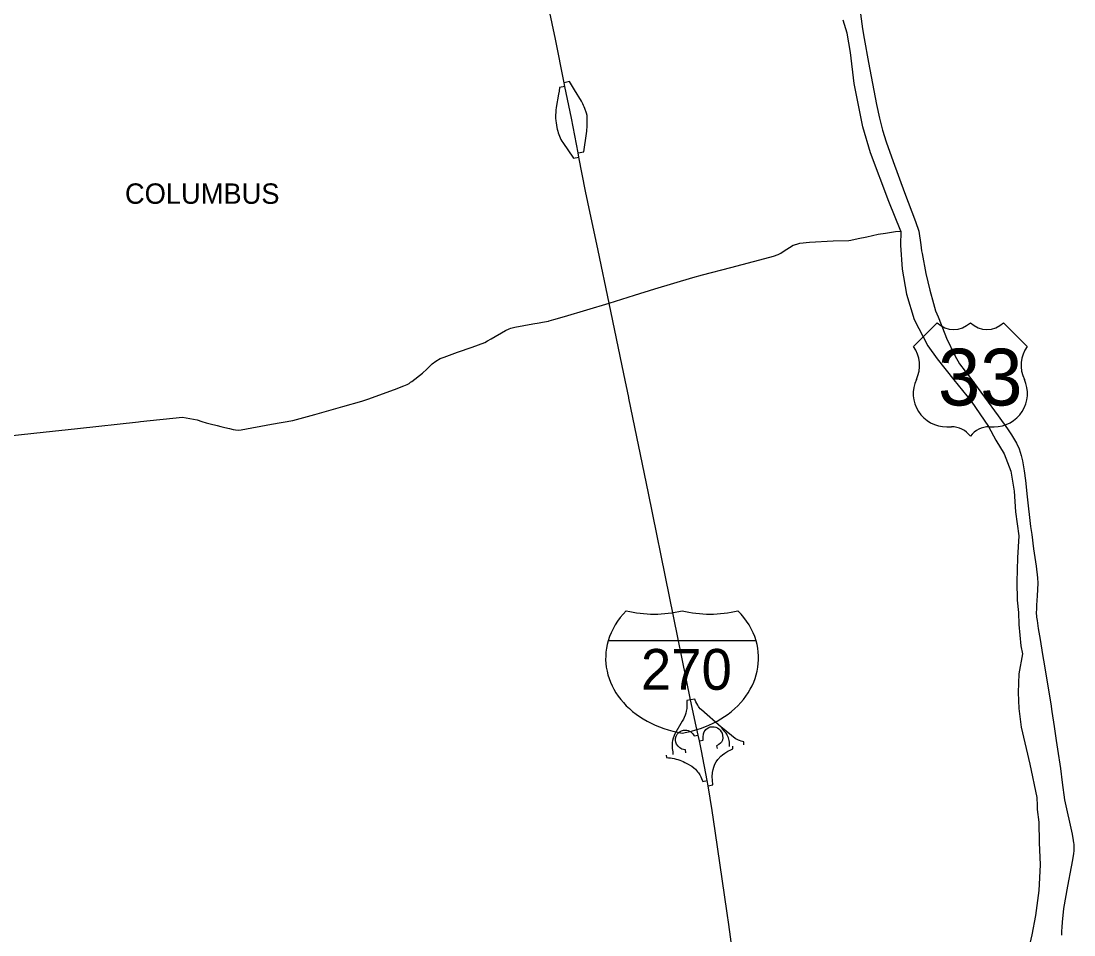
# Model space of a CAD drawing. Extents: x -1146 to -445, y -1283 to -822.
# Drawn here: x -1012.2 to -947.7, y -1003.9 to -947.9 of the extents above; entities that cross this region are included whole.
import ezdxf

# ---------------------------------------------------------------- set-up
doc = ezdxf.new("R2010")
doc.units = 0
for name, color, linetype in [('GM_X_Corporation_Text', 7, 'Continuous'), ('GM_X_Interchange_Ramps', 7, 'Continuous'), ('GM_X_Interstate_Route', 7, 'Continuous'), ('GM_X_Interstate_Shield', 7, 'Continuous'), ('GM_X_Township', 7, 'Continuous'), ('GM_X_US_Route', 7, 'Continuous'), ('GM_X_US_Shield', 7, 'Continuous')]:
    doc.layers.add(name, color=color, linetype=linetype)

msp = doc.modelspace()

# ---------------------------------------------------------------- linework, layer by layer
at = {"layer": 'GM_X_Interchange_Ramps'}
for points in [[(-978.902, -951.89), (-979.229, -951.959), (-979.255, -952.192), (-979.289, -952.371), (-979.433, -953.182), (-979.457, -953.352), (-979.468, -953.51), (-979.47, -953.61), (-979.477, -953.836), (-979.465, -954.004)], [(-977.548, -953.678), (-977.581, -953.535), (-977.686, -953.251), (-977.723, -953.152), (-977.762, -953.058), (-977.811, -952.953), (-977.896, -952.795), (-978.31, -952.113), (-978.444, -951.905), (-978.629, -951.601), (-978.945, -951.667)], [(-979.465, -954.004), (-979.447, -954.123), (-979.396, -954.415), (-979.375, -954.521), (-979.346, -954.638), (-979.316, -954.74), (-979.281, -954.84), (-979.242, -954.937), (-979.196, -955.04), (-979.143, -955.144), (-979.085, -955.245), (-979.034, -955.326), (-978.369, -956.3), (-978.043, -956.235)], [(-978.094, -955.977), (-977.747, -955.908), (-977.587, -954.786), (-977.564, -954.641), (-977.552, -954.528), (-977.546, -954.407), (-977.531, -953.796), (-977.548, -953.678)], [(-971.203, -989.506), (-971.428, -989.551), (-971.423, -989.758), (-971.426, -989.925), (-971.437, -990.045), (-971.461, -990.194), (-971.491, -990.321), (-971.531, -990.45), (-971.586, -990.591), (-971.631, -990.687), (-971.707, -990.824), (-972.176, -991.636), (-972.228, -991.751), (-972.268, -991.863), (-972.302, -991.991), (-972.324, -992.126), (-972.333, -992.232), (-972.333, -992.366), (-972.322, -992.487), (-972.307, -992.589), (-972.285, -992.705), (-972.279, -992.86)], [(-967.926, -992.257), (-967.944, -992.072), (-968.097, -992.038), (-968.192, -992.009), (-968.269, -991.979), (-968.342, -991.946), (-968.399, -991.917), (-968.466, -991.877), (-969.249, -991.238), (-969.318, -991.181), (-970.536, -990.128), (-970.605, -990.054), (-970.663, -989.983), (-970.718, -989.909), (-970.763, -989.843), (-970.823, -989.741), (-970.878, -989.633), (-970.921, -989.53), (-970.948, -989.456), (-971.203, -989.506)], [(-971.499, -992.755), (-971.519, -992.581), (-971.633, -992.557), (-971.741, -992.525), (-971.854, -992.449), (-971.965, -992.356), (-972.061, -992.229), (-972.108, -992.106), (-972.126, -991.995), (-972.123, -991.882), (-972.086, -991.738), (-972.014, -991.606), (-971.925, -991.509), (-971.841, -991.447), (-971.75, -991.402), (-971.632, -991.37), (-971.519, -991.362), (-971.428, -991.371), (-971.34, -991.394), (-971.266, -991.425), (-971.183, -991.476), (-971.12, -991.528), (-971.069, -991.585), (-970.979, -991.714), (-970.739, -991.665)], [(-970.66, -992.018), (-970.426, -991.97), (-970.432, -991.791), (-970.404, -991.583), (-970.36, -991.471), (-970.308, -991.388), (-970.255, -991.327), (-970.175, -991.259), (-970.083, -991.206), (-969.99, -991.172), (-969.887, -991.153), (-969.757, -991.156), (-969.644, -991.182), (-969.542, -991.227), (-969.471, -991.275), (-969.381, -991.361), (-969.314, -991.46), (-969.272, -991.555), (-969.244, -991.688), (-969.222, -991.838), (-969.251, -991.984), (-969.306, -992.094), (-969.371, -992.164), (-969.464, -992.249), (-969.603, -992.33), (-969.571, -992.487)], [(-968.806, -992.368), (-968.804, -992.254), (-968.817, -992.109), (-968.838, -991.998), (-968.862, -991.911), (-968.883, -991.836), (-968.913, -991.754), (-968.949, -991.673), (-968.98, -991.615), (-969.024, -991.544), (-969.113, -991.44), (-969.273, -991.268), (-969.249, -991.238)], [(-970.12, -994.772), (-969.838, -994.718), (-969.858, -994.436), (-969.874, -994.234), (-969.855, -993.954), (-969.818, -993.772), (-969.776, -993.631), (-969.704, -993.453), (-969.624, -993.3), (-969.538, -993.168), (-969.336, -992.965), (-969.237, -992.875), (-969.094, -992.77), (-968.913, -992.656), (-968.727, -992.566), (-968.599, -992.519), (-968.613, -992.35)], [(-972.697, -992.909), (-972.683, -993.041), (-972.547, -993.054), (-972.435, -993.069), (-972.329, -993.087), (-972.206, -993.112), (-972.074, -993.146), (-971.98, -993.173), (-971.864, -993.212), (-971.754, -993.253), (-971.657, -993.294), (-971.559, -993.339), (-971.339, -993.449), (-971.204, -993.525), (-971.118, -993.584), (-971.001, -993.674), (-970.906, -993.762), (-970.828, -993.843), (-970.769, -993.913), (-970.712, -993.988), (-970.638, -994.099), (-970.571, -994.219), (-970.521, -994.325), (-970.451, -994.507), (-970.176, -994.455)]]:
    msp.add_lwpolyline(points, dxfattribs=at)
at = {"layer": 'GM_X_Interstate_Route'}
for points in [[(-979.49, -949.004), (-979.884, -947.081), (-980.177, -945.769), (-980.263, -945.188), (-980.367, -944.616), (-980.484, -942.98), (-980.405, -941.443), (-980.386, -941.163)], [(-978.506, -953.838), (-978.902, -951.89), (-978.945, -951.667), (-979.49, -949.004)], [(-977.488, -959.001), (-977.635, -958.312), (-978.043, -956.235), (-978.094, -955.977), (-978.506, -953.838)], [(-974.985, -971.008), (-974.992, -970.975), (-975.291, -969.52), (-976.187, -965.178), (-976.855, -961.954), (-977.488, -959.001)], [(-970.855, -991.125), (-971.203, -989.506), (-973.781, -976.839), (-974.985, -971.008)], [(-969.693, -997.542), (-969.875, -996.286), (-970.12, -994.772), (-970.176, -994.455), (-970.538, -992.624), (-970.66, -992.018), (-970.739, -991.665), (-970.855, -991.125)], [(-968.962, -1002.587), (-969.693, -997.542)], [(-968.205, -1008.272), (-968.452, -1006.317), (-968.86, -1003.29), (-968.962, -1002.587)]]:
    msp.add_lwpolyline(points, dxfattribs=at)
at = {"layer": 'GM_X_Interstate_Shield'}
msp.add_line((-967.187, -985.881), (-976.252, -985.881), dxfattribs=at)
msp.add_line((-967.187, -985.881), (-976.252, -985.881), dxfattribs=at)
for centre, start_param, end_param in [((-970.547, -986.953), 2.47259, 2.911027), ((-973.431, -979.563), 4.415841, 5.008937), ((-970.007, -979.563), 4.415841, 5.008937), ((-972.891, -986.953), 0.230566, 0.669003), ((-970.547, -986.953), 2.911027, 4.511031), ((-972.891, -986.953), 4.913747, 6.513751)]:
    msp.add_ellipse(centre, major_axis=(5.859, 0), ratio=0.8, start_param=start_param, end_param=end_param, dxfattribs=at)
at = {"layer": 'GM_X_Township'}
for points in [[(-958.301, -960.779), (-959.042, -958.944), (-960.168, -955.964), (-960.639, -954.377), (-961.16, -951.715), (-961.399, -949.811), (-961.592, -948.622), (-961.837, -947.824)], [(-1016.586, -973.717), (-1010.894, -973.097), (-1008.792, -972.869), (-1005.045, -972.46), (-1004.929, -972.447), (-1002.344, -972.166), (-1001.448, -972.33), (-1001.167, -972.438), (-1000.888, -972.52), (-1000.651, -972.583), (-1000.227, -972.682), (-1000.002, -972.738), (-999.753, -972.801), (-999.475, -972.869), (-999.25, -972.926), (-999.095, -972.954), (-998.9, -972.965), (-998.746, -972.954), (-996.885, -972.611), (-995.587, -972.37), (-994.232, -972.007), (-992.512, -971.522), (-991.36, -971.193), (-990.928, -971.046), (-990.536, -970.91), (-989.36, -970.47), (-988.782, -970.257), (-988.57, -970.163), (-988.46, -970.102), (-988.359, -970.038), (-988.294, -969.991), (-987.637, -969.469), (-987.378, -969.224), (-987.036, -968.913), (-986.824, -968.743), (-986.541, -968.581), (-986.308, -968.49), (-985.479, -968.199), (-984.586, -967.875), (-983.822, -967.587), (-983.642, -967.5), (-983.419, -967.381), (-982.538, -966.868), (-982.328, -966.762), (-982.216, -966.718), (-982.127, -966.688), (-981.975, -966.651), (-980.865, -966.461), (-980.476, -966.395), (-980.28, -966.359), (-979.918, -966.286), (-979.876, -966.272), (-979.575, -966.186), (-978.938, -965.996), (-976.187, -965.178), (-974.645, -964.693), (-973.38, -964.31), (-971.069, -963.614), (-970.459, -963.453), (-968.73, -962.993), (-966.654, -962.445), (-966.116, -962.308), (-965.838, -962.2), (-965.673, -962.114), (-965.466, -961.974), (-965.143, -961.764), (-964.903, -961.633), (-964.694, -961.557), (-964.507, -961.511), (-963.906, -961.441), (-962.459, -961.37), (-961.507, -961.333), (-961.371, -961.313), (-960.918, -961.225), (-960.393, -961.116), (-959.692, -960.954), (-959.252, -960.884), (-958.631, -960.797), (-958.301, -960.779), (-958.326, -961.637), (-958.223, -963.1), (-957.965, -964.633), (-957.501, -966.183), (-956.658, -967.802), (-956.073, -968.594), (-955.057, -969.885), (-953.99, -971.194), (-952.94, -972.744), (-952.476, -973.587), (-951.977, -974.431), (-951.564, -975.481), (-951.357, -976.704), (-951.271, -977.978), (-951.065, -979.441), (-951.151, -980.801), (-951.203, -982.264), (-951.168, -983.401), (-951.099, -984.158), (-951.065, -984.881), (-950.944, -986.189), (-950.841, -986.689), (-951.082, -987.911), (-951.117, -989.047), (-951.065, -990.028), (-950.927, -991.173), (-950.393, -993.445), (-949.98, -995.493), (-949.958, -995.976), (-949.946, -996.233), (-949.842, -997.008), (-949.825, -998.247), (-949.773, -999.624), (-949.859, -1001.191), (-950.049, -1002.74), (-950.272, -1003.919), (-950.445, -1004.625)]]:
    msp.add_lwpolyline(points, dxfattribs=at)
at = {"layer": 'GM_X_US_Route'}
for points in [[(-960.465, -944.278), (-960.574, -945.025), (-960.737, -946.194), (-960.818, -946.864), (-960.818, -947.143), (-960.748, -947.757), (-960.658, -948.354), (-960.565, -948.953), (-960.291, -950.433), (-959.801, -952.995), (-959.626, -953.835), (-959.44, -954.578), (-959.218, -955.3), (-958.774, -956.5), (-958.078, -958.39), (-957.411, -960.17), (-957.208, -960.774)], [(-957.208, -960.774), (-957.086, -961.599), (-957.033, -961.977), (-957.006, -962.146), (-956.781, -963.373)], [(-956.781, -963.373), (-956.529, -964.391), (-956.315, -965.206), (-956.174, -965.653), (-956.03, -966.024), (-955.613, -967.06), (-955.513, -967.323), (-954.997, -968.392), (-954.716, -968.903), (-954.02, -969.808), (-952.333, -972.084), (-951.763, -972.885), (-951.524, -973.25), (-951.209, -973.773), (-951.051, -974.124), (-950.923, -974.521), (-950.853, -974.853), (-950.758, -975.465), (-950.673, -976.062), (-950.554, -977.052), (-950.354, -978.885), (-950.287, -979.376)], [(-950.287, -979.376), (-950.174, -980.24), (-950.02, -981.305), (-949.935, -982.03), (-949.918, -982.36), (-949.959, -983.132), (-949.988, -983.711), (-950.001, -983.92), (-950.006, -984.18), (-949.989, -984.403), (-949.983, -984.445)], [(-949.983, -984.445), (-949.958, -984.643), (-949.882, -985.137), (-949.758, -985.808), (-949.622, -986.722), (-949.557, -987.078), (-949.442, -987.8), (-949.244, -989.035), (-949.112, -989.758), (-949.044, -990.218), (-948.91, -991.134), (-948.778, -992.002), (-948.706, -992.535), (-948.53, -993.717), (-948.42, -994.567), (-948.266, -995.636)], [(-948.266, -995.636), (-948.266, -995.636), (-947.804, -997.743), (-947.737, -998.129), (-947.717, -998.268), (-947.707, -998.364), (-947.696, -998.488), (-947.696, -998.628), (-947.702, -998.766), (-947.723, -998.936), (-947.786, -999.322), (-947.869, -999.743), (-948.096, -1000.941), (-948.339, -1002.298), (-948.363, -1002.522), (-948.414, -1003.124), (-948.433, -1003.463), (-948.45, -1003.664), (-948.468, -1003.933)]]:
    msp.add_lwpolyline(points, dxfattribs=at)
at = {"layer": 'GM_X_US_Shield'}
for p, q in [((-956.078, -966.382), (-957.528, -967.832)), ((-950.567, -967.832), (-952.017, -966.382)), ((-955.498, -972.763), (-955.208, -972.763)), ((-952.887, -972.763), (-952.597, -972.763))]:
    msp.add_line(p, q, dxfattribs=at)
for centre, radius, start, end in [((-955.063, -965.346), 1.45, 225.573, 314.427), ((-953.032, -965.346), 1.45, 225.573, 314.427), ((-959.191, -968.997), 2.03, 334.54712, 35.00093), ((-948.904, -968.997), 2.03, 144.99907, 205.45288), ((-955.52, -970.733), 2.03, 154.83192, 270.63826), ((-952.575, -970.733), 2.03, 269.36174, 25.16808), ((-955.208, -974.213), 1.45, 36.8699, 90), ((-952.887, -974.213), 1.45, 90, 143.1301)]:
    msp.add_arc(centre, radius, start, end, dxfattribs=at)

# ---------------------------------------------------------------- texts
at = {"layer": 'GM_X_Corporation_Text'}
msp.add_text('COLUMBUS', height=1.25, rotation=0.00001, dxfattribs=at).set_placement((-1005.874, -959.092))
at = {"layer": 'GM_X_Interstate_Shield'}
msp.add_text('270', height=2.5, dxfattribs=at).set_placement((-974.244, -988.889))
at = {"layer": 'GM_X_US_Shield'}
msp.add_text('33', height=3.4805, dxfattribs=at).set_placement((-956.029, -971.458))

doc.saveas('drawing.dxf')
